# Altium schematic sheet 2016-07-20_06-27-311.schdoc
size 237 x 111 mm; SheetNumber: 1; SheetTotal: 1
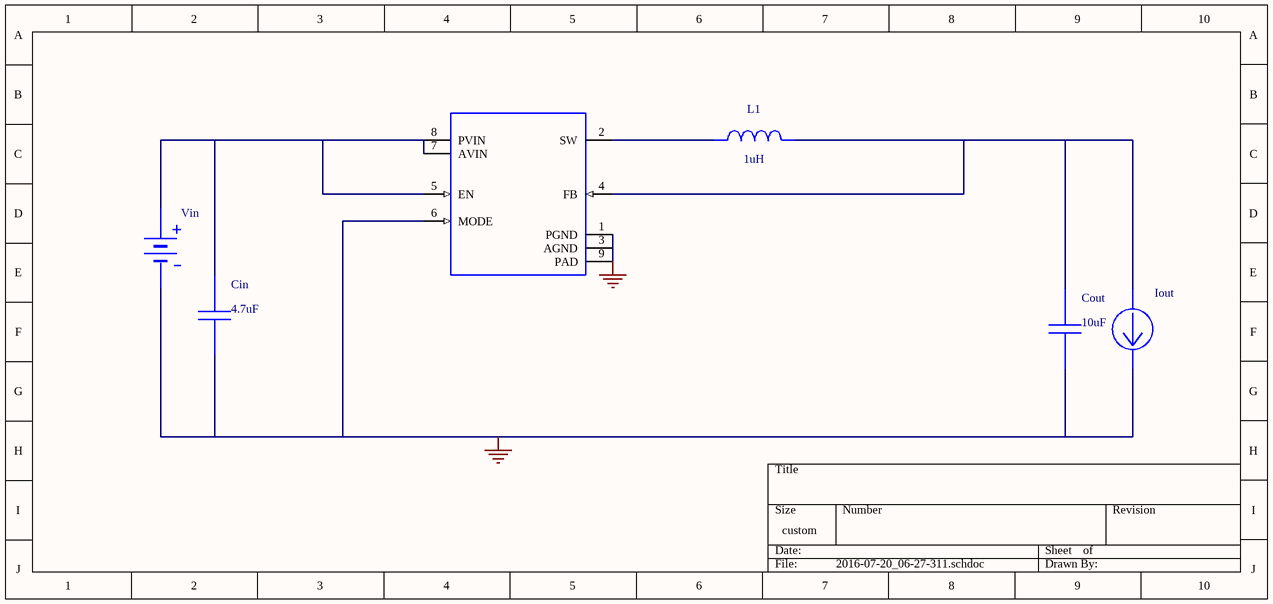
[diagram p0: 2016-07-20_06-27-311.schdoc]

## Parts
Cin  value 4.7uF  (hidden comment: GRM21BC81E475KA12L)
Cout  value 10uF  (hidden comment: GRM188R60J106ME47D)
Iout  WB_CURRENT_LOAD  (value not drawn)
L1  value 1uH  (hidden comment: IHLP1212AEER1R0M11)
U1  TPS62061DSGR  (value not drawn)
Vin  WB_BATTERY  (value not drawn)

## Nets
0: Cin.2 Cout.2 Iout.2(-) U1.1(PGND) U1.3(AGND) U1.6(MODE) U1.9(PAD) Vin.2(-)
NetCin_1: Cin.1 U1.5(EN) U1.7(AVIN) U1.8(PVIN) Vin.1(+)
NetCout_1: Cout.1 Iout.1(+) L1.2 U1.4(FB)
NetL1_1: L1.1 U1.2(SW)

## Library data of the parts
Cin = GRM21BC81E475KA12L: GRM21BC81E475KA1; Manufacturer Name: MuRata
Cout = GRM188R60J106ME47D: GRM188R60J106ME4; Manufacturer Name: MuRata
L1 = IHLP1212AEER1R0M11: Unknown; Manufacturer Name: Vishay-Dale
U1 = TPS62061DSGR: Manufacturer Name: Texas Instruments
